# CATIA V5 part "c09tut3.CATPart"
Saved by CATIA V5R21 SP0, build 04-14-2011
Part number: Part1
Bounding box of the stored display mesh (mm): x 0 to 224, y -87.701 to 88.896, z 0 to 67.047
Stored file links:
  D:\CATIA V5R21 E-RESOURCES\CATIA-V5R21\catia-v5r21-prt\c09-catia-v5r20-prt\c09-catia-v5r21-tut03.CATPart
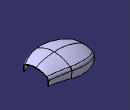
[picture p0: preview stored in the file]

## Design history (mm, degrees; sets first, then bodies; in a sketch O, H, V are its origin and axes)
Body1 (main body)
  Sketch1 on xy-plane, origin (0, 0, 0), H (1, 0, 0), V (0, 1, 0)
    arc A1 centre (95, -36.2404) radius 125 from (139.6655, 80.5072) to (0, 45) ccw
    point P1 (95, -36.2404)
    point P2 (0, 45)
    arc A2 centre (289.027, 470.911) radius 418 from (139.6655, 80.5072) to (224, 58) ccw
    point P5 (224, 58)
    radius A1 = 125
    radius A2 = 418
    distance H P2 = 45
    distance H P5 = 58
    distance P1 V = 95
    distance P2 P5 H = 224
    coincidence: P2 V
    tangency: A1 A2
  Sketch2 on xy-plane, origin (0, 0, 0), H (1, 0, 0), V (0, 1, 0)
    construction line L1 (0, -58) -> (224, -58)
    point P1 (0, -58)
    point P2 (224, -58)
    arc A1 centre (112, 154.264) radius 240 from (0, -58) to (224, -58) ccw
    length L1 = 224
    radius A1 = 240
    distance H L1 = 58
    coincidence: P1 V
    horizontal: L1 H
  Sketch3 on zx-plane, origin (0, 0, 0), H (-1, 0, 0), V (0, 0, 1)
    arc A1 centre (-126.7082, -167.9142) radius 235 from (-224, 46) to (0, 30) cw
    point P2 (0, 30)
    point P3 (-224, 46)
    radius A1 = 235
    distance H P2 = 30
    distance H P3 = 46
    distance P3 P2 H = 224
    coincidence: P2 V
  Sketch4 on yz-plane, origin (0, 0, 0), H (0, 1, 0), V (0, 0, 1)
    line L1 (-58, 0) -> (45, 0)
    point P1 (-58, 0)
    point P2 (45, 0)
    reference projected point E1 (-58, 0) from Sketch2.P1
    reference projected point E2 (45, 0) from Sketch1.P2
    construction line L2 (-58, 18.5632) -> (45, 18.5632)
    line L3 (-58, 0) -> (-58, 18.5632)
    line L4 (45, 0) -> (45, 18.5632)
    arc A1 centre (-6.5, -89.8238) radius 120 from (-58, 18.5632) to (45, 18.5632) cw
    reference projected point E3 (0, 30) from Sketch3.P2
    radius A1 = 120
    coincidence: P1 H, P1 E1, P2 E2, A1 E3
    horizontal: L2 H
    vertical: L3 V, L4 V
  Plane1: type 3Points, Element1 Sketch3.P3, Element2 Sketch2.P2, Element3 Sketch1.P5
  Sketch5 on Plane1, origin (224, 0, 0), H (0, 1, 0), V (0, 0, 1)
    line L1 (-58, 0) -> (58, 0)
    point P1 (-58, 0)
    point P2 (58, 0)
    reference projected point E1 (58, 0) from Sketch1.P5
    line L2 (-58, 0) -> (-58, 29.9794)
    line L3 (58, 0) -> (58, 29.9794)
    construction line L4 (-58, 29.9794) -> (58, 29.9794)
    reference projected point E2 (-58, 0) from Sketch2.P2
    arc A1 centre (0, -67) radius 113 from (-58, 29.9794) to (58, 29.9794) cw
    reference projected point E3 (0, 46) from Sketch3.P3
    radius A1 = 113
    coincidence: P1 H, E1 P2, E2 P1, A1 E3
    horizontal: L1 H, L4 H
    vertical: L2 V, L3 V
  Loft1: solid, Sections (Sketch4; Sketch5), Guides (Sketch1; Sketch3; Sketch2)
  Fillet1: radius 25, on edge [face of Loft1 | face of Loft1] (x2)
  Fillet2: radius 15, on edge [face of Loft1 | face of Loft1] (x3)
  Shell1: ExtOffset 0, Face (face of Loft1; face of Loft1), IntOffset 3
